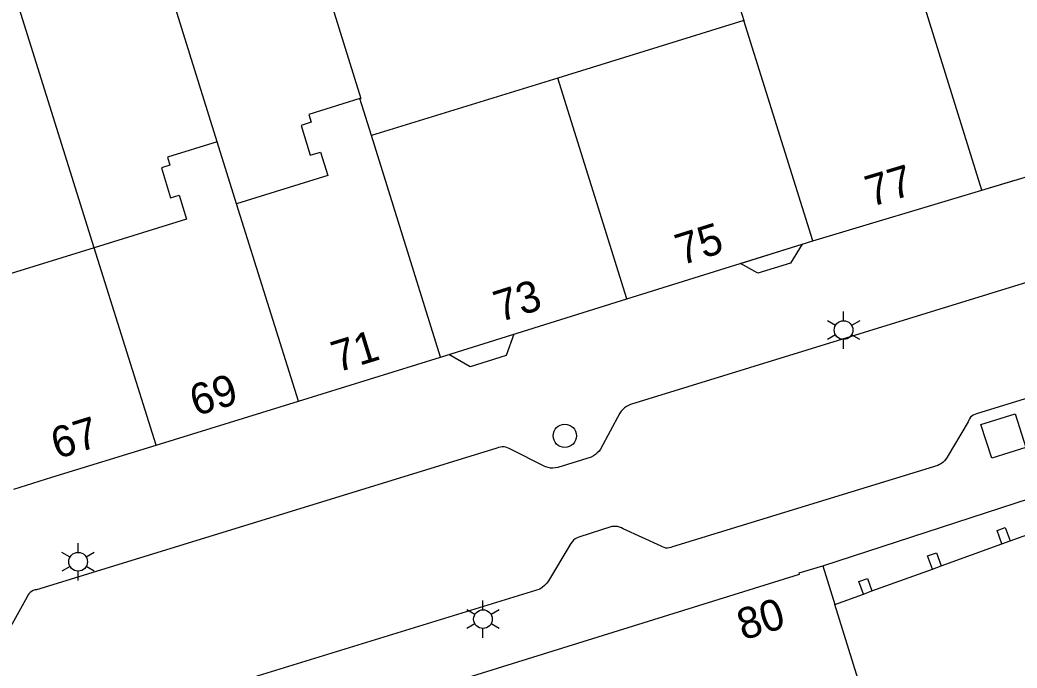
# Model space of a CAD drawing. Extents: x 122462 to 123306, y 485548 to 486417.
# Drawn here: x 122831.05 to 122879.04, y 485893.49 to 485924.68 of the extents above; entities that cross this region are included whole.
import ezdxf

# ---------------------------------------------------------------- set-up
doc = ezdxf.new("R2010")
doc.units = 0
for name, color, linetype in [('B-WE-IE-MEUBILAIR_WEGMEUBILAIR_VERKEERSBORD-S', 7, 'Continuous'), ('B-WE-OG-TOPOKAART-G', 7, 'Continuous'), ('Level 1', 7, 'Continuous'), ('Level 10', 7, 'Continuous'), ('Level 11', 7, 'Continuous'), ('Level 17', 7, 'Continuous'), ('Level 19', 7, 'Continuous'), ('Level 21', 7, 'Continuous'), ('Level 4', 7, 'Continuous'), ('Level 42', 7, 'Continuous'), ('Level 50', 7, 'Continuous'), ('Level 53', 7, 'Continuous')]:
    doc.layers.add(name, color=color, linetype=linetype)

msp = doc.modelspace()

# ---------------------------------------------------------------- linework, layer by layer
at = {"layer": 'B-WE-OG-TOPOKAART-G'}
msp.add_lwpolyline([(122877.355, 485916.488), (122886.989, 485919.37), (122887.932, 485921.215), (122885.12, 485929.269)], dxfattribs=at)
at = {"layer": 'Level 1'}
for p, q in [((122865.655, 485925.426), (122865.898, 485924.649)), ((122865.898, 485924.649), (122856.934, 485921.879)), ((122856.934, 485921.879), (122847.969, 485919.109)), ((122847.969, 485919.109), (122847.413, 485920.888)), ((122841.479, 485915.832), (122840.544, 485918.818)), ((122869.209, 485914.049), (122877.355, 485916.488)), ((122860.257, 485911.251), (122869.209, 485914.049)), ((122851.299, 485908.449), (122860.257, 485911.251)), ((122837.601, 485904.221), (122844.451, 485906.336)), ((122878.712, 485899.603), (122881.618, 485900.653)), ((122875.392, 485898.403), (122878.317, 485899.46)), ((122878.317, 485899.46), (122878.712, 485899.603)), ((122869.689, 485898.41), (122870.27, 485896.552)), ((122874.97, 485898.25), (122875.392, 485898.403)), ((122872.049, 485897.209), (122874.97, 485898.25)), ((122870.27, 485896.552), (122871.65, 485897.049)), ((122871.65, 485897.049), (122872.049, 485897.209))]:
    msp.add_line(p, q, dxfattribs=at)
for points in [[(122847.413, 485920.888), (122844.953, 485920.129), (122845.07, 485919.75), (122844.579, 485919.598), (122845.021, 485918.168), (122845.512, 485918.32), (122845.862, 485917.186), (122841.479, 485915.832)], [(122840.544, 485918.818), (122838.149, 485918.077), (122838.271, 485917.682), (122837.857, 485917.554), (122838.299, 485916.123), (122838.714, 485916.251), (122839.073, 485915.088), (122834.629, 485913.715)], [(122877.355, 485916.488), (122878.931, 485916.959)], [(122834.629, 485913.715), (122830.169, 485912.337), (122829.842, 485913.394), (122830.302, 485913.536), (122829.835, 485915.046), (122829.376, 485914.904), (122829.248, 485915.317), (122826.847, 485914.575)], [(122844.451, 485906.336), (122847.875, 485907.393), (122851.299, 485908.449)], [(122830.751, 485902.1), (122832.58, 485902.67), (122837.601, 485904.221)], [(122833.489, 485887.15), (122834.64, 485887.509), (122834.658, 485887.453), (122851.618, 485892.733), (122868.578, 485898.013), (122868.559, 485898.069), (122869.689, 485898.41)]]:
    msp.add_lwpolyline(points, dxfattribs=at)
at = {"layer": 'Level 10'}
msp.add_lwpolyline([(122866.571, 485912.483), (122865.726, 485912.961), (122868.695, 485913.89), (122868.144, 485912.974), (122866.571, 485912.483)], dxfattribs=at)
at = {"layer": 'Level 11'}
msp.add_lwpolyline([(122854.826, 485909.553), (122854.453, 485908.527), (122852.719, 485907.985), (122851.687, 485908.572)], dxfattribs=at)
at = {"layer": 'Level 17'}
for points in [[(122880.383, 485912.32), (122860.443, 485906.163), (122860.339, 485906.122), (122860.241, 485906.069), (122860.149, 485906.005), (122860.066, 485905.93), (122859.993, 485905.846), (122859.93, 485905.754), (122858.993, 485904.024), (122858.922, 485903.927), (122858.84, 485903.838), (122858.749, 485903.76), (122858.65, 485903.692), (122858.543, 485903.636), (122856.936, 485903.146), (122856.821, 485903.119), (122856.703, 485903.108), (122856.584, 485903.113), (122856.467, 485903.132), (122856.354, 485903.167), (122854.596, 485904.045), (122854.519, 485904.086), (122854.436, 485904.115), (122854.35, 485904.131), (122854.263, 485904.135), (122854.176, 485904.125), (122854.091, 485904.102), (122854.011, 485904.067), (122849.109, 485902.56), (122831.854, 485897.257), (122831.768, 485897.245), (122831.686, 485897.218), (122831.609, 485897.178), (122831.54, 485897.126), (122831.481, 485897.063), (122831.433, 485896.992), (122831.397, 485896.913), (122830.43, 485895.176)], [(122881.978, 485907.229), (122877.096, 485905.714), (122877.015, 485905.693), (122876.938, 485905.658), (122876.868, 485905.612), (122876.807, 485905.554), (122876.756, 485905.488), (122876.717, 485905.414), (122876.69, 485905.334), (122875.675, 485903.631), (122875.622, 485903.543), (122875.559, 485903.463), (122875.486, 485903.391), (122875.405, 485903.329), (122875.317, 485903.277), (122875.223, 485903.236), (122862.46, 485899.322), (122862.384, 485899.288), (122862.304, 485899.267), (122862.221, 485899.259), (122862.138, 485899.264), (122862.057, 485899.283), (122861.98, 485899.314), (122861.909, 485899.357), (122860.085, 485900.194), (122860.001, 485900.238), (122859.912, 485900.272), (122859.819, 485900.295), (122859.725, 485900.306), (122859.63, 485900.307), (122859.535, 485900.296), (122857.955, 485899.788), (122857.863, 485899.749), (122857.778, 485899.698), (122857.699, 485899.637), (122857.629, 485899.566), (122857.568, 485899.487), (122857.518, 485899.401), (122856.496, 485897.683), (122856.404, 485897.57), (122856.302, 485897.465), (122856.191, 485897.37), (122856.072, 485897.286), (122850.865, 485895.683), (122833.972, 485890.481)], [(122869.689, 485898.41), (122887.52, 485904.209), (122891.121, 485905.18)]]:
    msp.add_lwpolyline(points, dxfattribs=at)
at = {"layer": 'Level 19'}
for p, q in [((122840.544, 485918.818), (122837.063, 485929.936)), ((122834.629, 485913.715), (122830.218, 485927.805))]:
    msp.add_line(p, q, dxfattribs=at)
msp.add_lwpolyline([(122843.973, 485932.088), (122847.456, 485920.901), (122847.413, 485920.888)], dxfattribs=at)
at = {"layer": 'Level 21'}
for points in [[(122878.317, 485899.46), (122878.084, 485900.102), (122878.478, 485900.246), (122878.712, 485899.603)], [(122874.97, 485898.25), (122874.739, 485898.883), (122875.161, 485899.037), (122875.392, 485898.403)], [(122871.65, 485897.049), (122871.433, 485897.656), (122871.838, 485897.802), (122872.049, 485897.209)]]:
    msp.add_lwpolyline(points, dxfattribs=at)
at = {"layer": 'Level 4'}
for p, q in [((122877.355, 485916.488), (122874.382, 485925.999)), ((122869.209, 485914.049), (122865.898, 485924.649)), ((122860.257, 485911.251), (122856.934, 485921.879)), ((122851.299, 485908.449), (122847.969, 485919.109)), ((122844.451, 485906.336), (122841.479, 485915.832)), ((122837.601, 485904.221), (122834.629, 485913.715))]:
    msp.add_line(p, q, dxfattribs=at)
msp.add_lwpolyline([(122875.729, 485880.584), (122875.296, 485880.41), (122870.27, 485896.552)], dxfattribs=at)
at = {"layer": 'Level 42'}
msp.add_lwpolyline([(122877.823, 485903.58), (122877.306, 485905.201), (122878.951, 485905.725), (122879.468, 485904.104), (122877.823, 485903.58)], dxfattribs=at)
at = {"layer": 'Level 50'}
for p, q in [((122870.693, 485910.202), (122870.693, 485910.652)), ((122870.303, 485909.977), (122869.913, 485910.202)), ((122871.472, 485910.202), (122871.082, 485909.977)), ((122870.303, 485909.527), (122869.913, 485909.302)), ((122871.472, 485909.302), (122871.082, 485909.527)), ((122870.693, 485908.852), (122870.693, 485909.302)), ((122833.851, 485899.054), (122833.851, 485899.504)), ((122833.461, 485898.829), (122833.071, 485899.054)), ((122834.63, 485899.054), (122834.24, 485898.829)), ((122833.461, 485898.379), (122833.071, 485898.154)), ((122834.63, 485898.154), (122834.24, 485898.379)), ((122833.851, 485897.704), (122833.851, 485898.154)), ((122853.337, 485896.291), (122853.337, 485896.741)), ((122852.947, 485896.066), (122852.557, 485896.291)), ((122854.116, 485896.291), (122853.726, 485896.066)), ((122852.947, 485895.616), (122852.557, 485895.391)), ((122854.116, 485895.391), (122853.726, 485895.616)), ((122853.337, 485894.941), (122853.337, 485895.391))]:
    msp.add_line(p, q, dxfattribs=at)
for centre in [(122870.693, 485909.752), (122833.851, 485898.604), (122853.337, 485895.841)]:
    msp.add_circle(centre, 0.45, dxfattribs=at)
at = {"layer": 'Level 53'}
msp.add_circle((122857.275, 485904.664), 0.56, dxfattribs=at)

# ---------------------------------------------------------------- texts
at = {"layer": 'B-WE-IE-MEUBILAIR_WEGMEUBILAIR_VERKEERSBORD-S'}
for s, rotation, p in [('77', 16.6693, (122872.009, 485915.67)), ('75', 17.3551, (122862.882, 485912.858)), ('73', 17.3606, (122854.139, 485910.123)), ('71', 17.1553, (122846.32, 485907.7)), ('69', 17.1553, (122839.512, 485905.598)), ('67', 17.1553, (122832.831, 485903.534)), ('80', 17.2776, (122865.855, 485894.81))]:
    msp.add_text(s, height=1.5, rotation=rotation, dxfattribs=at).set_placement(p)

doc.saveas('drawing.dxf')
